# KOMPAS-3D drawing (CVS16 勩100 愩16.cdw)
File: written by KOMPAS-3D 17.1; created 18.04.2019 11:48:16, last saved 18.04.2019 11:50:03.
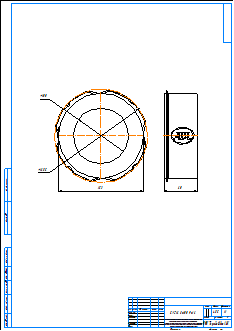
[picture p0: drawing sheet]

Sheet 1: A2, portrait

Title block, sheet 1: name: CVS16 Ду100 Ру16; material: Внимание! Данный продукт является объектом авторского права ООО «Торговый Дом АДЛ». / Запрещается изменение, копирование, распространение / (в том числе путем копирования на другие сайты и ресурсы в Интернете) / или любое иное использование информации и объектов без предварительного / согласия правообладателя (ООО «Торговый Дом АДЛ»).; mass: 4,85; sheets: 1; organisation: ООО "Торговый дом АДЛ"; sheet format: A2

Views: Вид 1, Проекционный вид 2
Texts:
  user
Dimensions and other numbers on the sheet: 153; 168,5; 100; 60; 1:1; 1; 4,85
